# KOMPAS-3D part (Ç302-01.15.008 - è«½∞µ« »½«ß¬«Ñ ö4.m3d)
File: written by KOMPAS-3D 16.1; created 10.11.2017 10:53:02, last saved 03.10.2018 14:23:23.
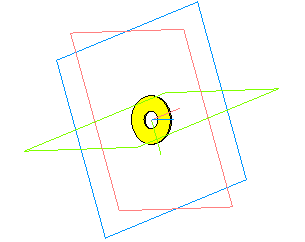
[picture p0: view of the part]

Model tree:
1. Эскиз:1
2. Операция выдавливания:1  (labels: Фторопласт-4  ГОСТ 10007-80 Е)
     Расстояние 1 = 0.5

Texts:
  Кольцо плоское уплотнительное 5-13-10 Ф4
